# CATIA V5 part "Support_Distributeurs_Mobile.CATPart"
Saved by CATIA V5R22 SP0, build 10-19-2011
Part number: Support_Distributeurs_Mobile
Bounding box of the stored display mesh (mm): x -25 to 25, y 0 to 46, z -47.5 to 47.5
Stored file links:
  U:\S9A\PER\CAO\Assemblage\Cadre\Chariot_Y\Support_Distributeurs_Mobile.CATPart
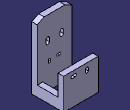
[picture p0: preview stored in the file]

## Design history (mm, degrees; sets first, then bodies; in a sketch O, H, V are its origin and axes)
Body1 (main body)
  Sketch1 on zx-plane, origin (0, 0, 0), H (-1, 0, 0), V (0, 0, 1)
    point P1 (-25, 47.5)
    line L1 (-25, 47.5) -> (25, 47.5)
    line L2 (25, 47.5) -> (25, -47.5)
    line L3 (25, -47.5) -> (-25, -47.5)
    line L4 (-25, -47.5) -> (-25, 47.5)
    point P2 (25, 47.5)
    point P4 (-25, -47.5)
    length L1 = 50
    length L4 = 95
    horizontal: L1 H, L3 H
    vertical: L2 V, L4 V
    symmetry: P1 P2 V, P4 P1 H
  Pad1: profile Sketch1, direction (0, 1, 0), length 8
  Sketch2 on end face of Pad1, origin (0, 8, 0), H (-1, 0, 0), V (0, 0, 1)
    point P1 (-25, -32.5)
    line L1 (-25, -32.5) -> (-17, -32.5)
    line L2 (-17, -32.5) -> (-17, -47.5)
    line L3 (-17, -47.5) -> (-25, -47.5)
    line L4 (-25, -47.5) -> (-25, -32.5)
    point P2 (-17, -32.5)
    point P3 (-17, -47.5)
    point P4 (-25, -47.5)
    reference projected line E1 (-25, 47.5) -> (-25, -47.5) from edge [face of Pad1 from Sketch1.L4 | end face of Pad1]
    reference projected line E2 (-25, -47.5) -> (25, -47.5) from edge [face of Pad1 from Sketch1.L3 | end face of Pad1]
    reference projected line E3 (-25, -47.5) -> (25, -47.5) from edge [face of Pad1 from Sketch1.L3 | end face of Pad1]
    point P5 (25, -32.5)
    point P6 (17, -32.5)
    point P7 (17, -47.5)
    point P8 (25, -47.5)
    line L5 (25, -32.5) -> (17, -32.5)
    line L6 (17, -32.5) -> (17, -47.5)
    line L7 (17, -47.5) -> (25, -47.5)
    line L8 (25, -47.5) -> (25, -32.5)
    distance L1 E2 = 15
    length L1 = 8
    horizontal: L1 H, L3 H
    vertical: L2 V, L4 V
    coincidence: E1 L4, L3 E3
    symmetry: P1 P5 V, P2 P6 V, P3 P7 V, P4 P8 V, L1 L5 V, L2 L6 V, L3 L7 V, L4 L8 V
  Pad2: profile Sketch2, direction (0, 1, 0), length 30
  Sketch3 on end face of Pad2, origin (0, 38, 0), H (-1, 0, 0), V (0, 0, 1)
    line L1 (-25, -47.5) -> (25, -47.5)
    line L2 (25, -47.5) -> (25, -32.5)
    line L3 (25, -32.5) -> (-25, -32.5)
    line L4 (-25, -32.5) -> (-25, -47.5)
    reference projected line E1 (-17, -32.5) -> (-25, -32.5) from edge [face of Pad2 from Sketch2.L1 | end face of Pad2]
    reference projected line E2 (17, -47.5) -> (25, -47.5) from edge [face of Pad2 | end face of Pad2]
    reference projected line E4 (-25, -32.5) -> (-25, -47.5) from edge [face of Pad2 | end face of Pad2]
    reference projected line E5 (25, -47.5) -> (25, -32.5) from edge [face of Pad2 | end face of Pad2]
    horizontal: L1 H, L3 H
    vertical: L2 V, L4 V
    coincidence: L3 E1, L1 E2, L4 E4, L2 E5
  Pad3: profile Sketch3, direction (0, 1, 0), length 8
  Sketch4 on end face of Pad1, origin (0, 8, 0), H (-1, 0, 0), V (0, 0, 1)
    arc A1 centre (-10, 13) radius 2.5 from (-12.5, 13) to (-7.5, 13) ccw
    arc A2 centre (-10, 18) radius 2.5 from (-7.5, 18) to (-12.5, 18) ccw
    point P2 (-10, 18)
    line L1 (-12.5, 13) -> (-12.5, 18)
    point P3 (-12.5, 13)
    point P4 (-12.5, 18)
    line L2 (-7.5, 13) -> (-7.5, 18)
    point P5 (-7.5, 13)
    point P6 (-7.5, 18)
    point P8 (10, 18)
    point P9 (12.5, 13)
    point P10 (12.5, 18)
    point P11 (7.5, 13)
    point P12 (7.5, 18)
    arc A3 centre (10, 13) radius 2.5 from (12.5, 13) to (7.5, 13) cw
    arc A4 centre (10, 18) radius 2.5 from (7.5, 18) to (12.5, 18) cw
    line L3 (12.5, 13) -> (12.5, 18)
    line L4 (7.5, 13) -> (7.5, 18)
    reference projected line E1 (25, 47.5) -> (-25, 47.5) from edge [face of Pad1 from Sketch1.L1 | end face of Pad1]
    radius A1 = 2.5
    length L1 = 5
    distance P2 P8 = 20
    distance E1 A2 = 27
    tangency: L1 A2, L2 A1, L1 A1, L2 A2
    vertical: L1 V, L2 V
    symmetry: P3 P9 V, P4 P10 V, P5 P11 V, P6 P12 V, A1 A3 V, A2 A4 V, L1 L3 V, L2 L4 V
  Pocket1: profile Sketch4, direction (0, -1, 0), through (limit type 6)
  Sketch5 on face of Pad3, origin (0, 0, -32.5), H (1, 0, 0), V (0, 1, 0)
    line L1 (-25, 46) -> (25, 46)
    line L2 (25, 46) -> (25, 38)
    line L3 (25, 38) -> (-25, 38)
    line L4 (-25, 38) -> (-25, 46)
    reference projected line E1 (-17, 38) -> (17, 38) from edge [start face of Pad3 | face of Pad3]
    reference projected line E2 (-25, 46) -> (25, 46) from edge [face of Pad3 | end face of Pad3]
    reference projected line E3 (-25, 8) -> (-25, 38) from edge [face of Pad3 | face of Pad3]
    reference projected line E4 (25, 8) -> (25, 38) from edge [face of Pad3 | face of Pad3]
    horizontal: L1 H, L3 H
    vertical: L2 V, L4 V
    coincidence: L3 E1, L1 E2, L4 E3, L2 E4
  Pad4: profile Sketch5, direction (0, 0, 1), length 30
  Sketch6 on face of Pad4, origin (0, 46, 0), H (-1, 0, 0), V (0, 0, 1)
    arc A1 centre (-8.5, -9.5) radius 2 from (-8.5, -11.5) to (-8.5, -7.5) ccw
    point P1 (-8.5, -9.5)
    point P2 (8.5, -9.5)
    arc A2 centre (8.5, -9.5) radius 2 from (6.5, -9.5) to (10.5, -9.5) cw
    reference projected line E1 (-25, -2.5) -> (25, -2.5) from edge [face of Pad4 | end face of Pad4]
    axis line L1 (8.5, -9.5) -> (-8.5, -9.5)
    arc A3 centre (-12.5, -9.5) radius 2 from (-12.5, -7.5) to (-12.5, -11.5) ccw
    point P3 (-12.5, -9.5)
    line L2 (-8.5, -7.5) -> (-12.5, -7.5)
    line L3 (-8.5, -11.5) -> (-12.5, -11.5)
    arc A4 centre (8.5, -13.5) radius 2 from (6.5, -13.5) to (10.5, -13.5) ccw
    point P8 (8.5, -13.5)
    line L4 (10.5, -9.5) -> (10.5, -13.5)
    point P9 (10.5, -9.5)
    line L5 (6.5, -9.5) -> (6.5, -13.5)
    point P11 (6.5, -9.5)
    point P13 (10.5, -9.5)
    point P14 (6.5, -9.5)
    radius A1 = 2
    distance E1 A1 = 5
    distance P1 P2 = 17
    distance P1 P3 = 4
    distance P8 P2 = 4
    symmetry: A1 A2 V, P1 P2 V
    horizontal: L1 H, L3 H
    coincidence: P3 L1, P9 A2, P11 A2, L5 P14, L4 P13
    tangency: L3 A1, L3 A3, L2 A3, L2 A1, L4 A2, A4 L4, L5 A4, L5 A2
    vertical: L4 V, L5 V
  Pocket2: profile Sketch6, direction (0, -1, 0), through (limit type 6)
  Chamfer1: length 10, second length 5, on edge [face of Pad1 from Sketch1.L1 | face of Pad4]; edge [face of Pad4 | face of Pad1 from Sketch1.L1]
  Sketch7 on end face of Pad1, origin (0, 8, 0), H (-1, 0, 0), V (0, 0, 1)
    projected arc E1 centre (-8.5, -9.5) radius 2 from (-8.5, -11.5) to (-8.5, -7.5) ccw from edge [face of Pad4 | face of Pocket2 from Sketch6.A1]
    projected arc E2 centre (8.5, -9.5) radius 2 from (10.5, -9.5) to (6.5, -9.5) ccw from edge [face of Pad4 | face of Pocket2 from Sketch6.A2]
    axis line L1 (-8.5, -9.5) -> (8.5, -9.5)
    point P1 (-8.5, -9.5)
    point P2 (8.5, -9.5)
    arc A1 centre (-7.5, -9.5) radius 1.5 from (-6, -9.5) to (-9, -9.5) ccw
    point P3 (-7.5, -9.5)
    arc A2 centre (7.5, -9.5) radius 1.5 from (7.5, -8) to (7.5, -11) cw
    arc A3 centre (4.5, -9.5) radius 1.5 from (4.5, -8) to (4.5, -11) ccw
    point P5 (4.5, -9.5)
    arc A4 centre (-7.5, -12.5) radius 1.5 from (-9, -12.5) to (-6, -12.5) ccw
    line L2 (7.5, -11) -> (4.5, -11)
    line L3 (-9, -9.5) -> (-9, -12.5)
    point P9 (-9, -9.5)
    line L4 (-6, -9.5) -> (-6, -12.5)
    point P11 (-6, -9.5)
    line L5 (4.5, -8) -> (7.5, -8)
    point P15 (-9, -9.5)
    point P16 (-6, -9.5)
    distance A2 A1 = 15
    radius A2 = 1.5
    length L5 = 3
    length L3 = 3
    concentricity: P1 E1, P2 E2
    horizontal: L1 H, L2 H
    coincidence: P3 L1, P5 L1, P9 A1, P11 A1, L1 P15, L1 P16
    symmetry: A1 A2 V
    tangency: L2 A2, L2 A3, L5 A2, A3 L5, L4 A1, A1 L3, L3 A4, L4 A4
    vertical: L3 V, L4 V
  Pocket3: profile Sketch7, direction (0, -1, 0), through (limit type 6)
  Sketch8 on end face of Pad1, origin (0, 8, 0), H (-1, 0, 0), V (0, 0, 1)
    point P1 (-25, 35)
    line L1 (-25, 35) -> (25, 35)
    line L2 (25, 35) -> (25, -35)
    line L3 (25, -35) -> (-25, -35)
    line L4 (-25, -35) -> (-25, 35)
    point P2 (25, 35)
    point P4 (-25, -35)
    length L1 = 50
    length L4 = 70
    horizontal: L1 H, L3 H
    vertical: L2 V, L4 V
    symmetry: P1 P2 V, P4 P1 H
  Pad5: profile Sketch8, direction (0, 1, 0), length 5
  Sketch9 on end face of Pad5, origin (0, 13, 0), H (-1, 0, 0), V (0, 0, 1)
    point P1 (-25, 35)
    line L1 (-25, 35) -> (25, 35)
    line L2 (25, 35) -> (25, -35)
    line L3 (25, -35) -> (-25, -35)
    line L4 (-25, -35) -> (-25, 35)
    point P2 (25, 35)
    point P4 (-25, -35)
    length L1 = 50
    length L4 = 70
    horizontal: L1 H, L3 H
    vertical: L2 V, L4 V
    symmetry: P1 P2 V, P4 P1 H
  Pad6: profile Sketch9, direction (0, 1, 0), length 5
  Sketch10 on end face of Pad6, origin (0, 18, 0), H (-1, 0, 0), V (0, 0, 1)
    point P1 (-25, 35)
    line L1 (-25, 35) -> (25, 35)
    line L2 (25, 35) -> (25, -35)
    line L3 (25, -35) -> (-25, -35)
    line L4 (-25, -35) -> (-25, 35)
    point P2 (25, 35)
    point P4 (-25, -35)
    length L1 = 50
    length L4 = 70
    horizontal: L1 H, L3 H
    vertical: L2 V, L4 V
    symmetry: P1 P2 V, P4 P1 H
  Pad7: profile Sketch10, direction (0, 1, 0), length 5
  Sketch11 on face of Pad4, origin (0, 46, 0), H (-1, 0, 0), V (0, 0, 1)
    line L1 (-25, -47.5) -> (25, -47.5)
    line L2 (25, -47.5) -> (25, -32.5)
    line L3 (25, -32.5) -> (-25, -32.5)
    line L4 (-25, -32.5) -> (-25, -47.5)
    reference projected line E1 (-17, -32.5) -> (-25, -32.5) from edge [face of Pad2 from Sketch2.L1 | end face of Pad2]
    reference projected line E2 (17, -47.5) -> (25, -47.5) from edge [face of Pad2 | end face of Pad2]
    reference projected line E4 (-25, -32.5) -> (-25, -47.5) from edge [face of Pad2 | end face of Pad2]
    reference projected line E5 (25, -47.5) -> (25, -32.5) from edge [face of Pad2 | end face of Pad2]
    horizontal: L1 H, L3 H
    vertical: L2 V, L4 V
    coincidence: L3 E1, L1 E2, L4 E4, L2 E5
  Pad8: profile Sketch11, direction (0, 1, 0), length 8
Current feature: Pocket3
